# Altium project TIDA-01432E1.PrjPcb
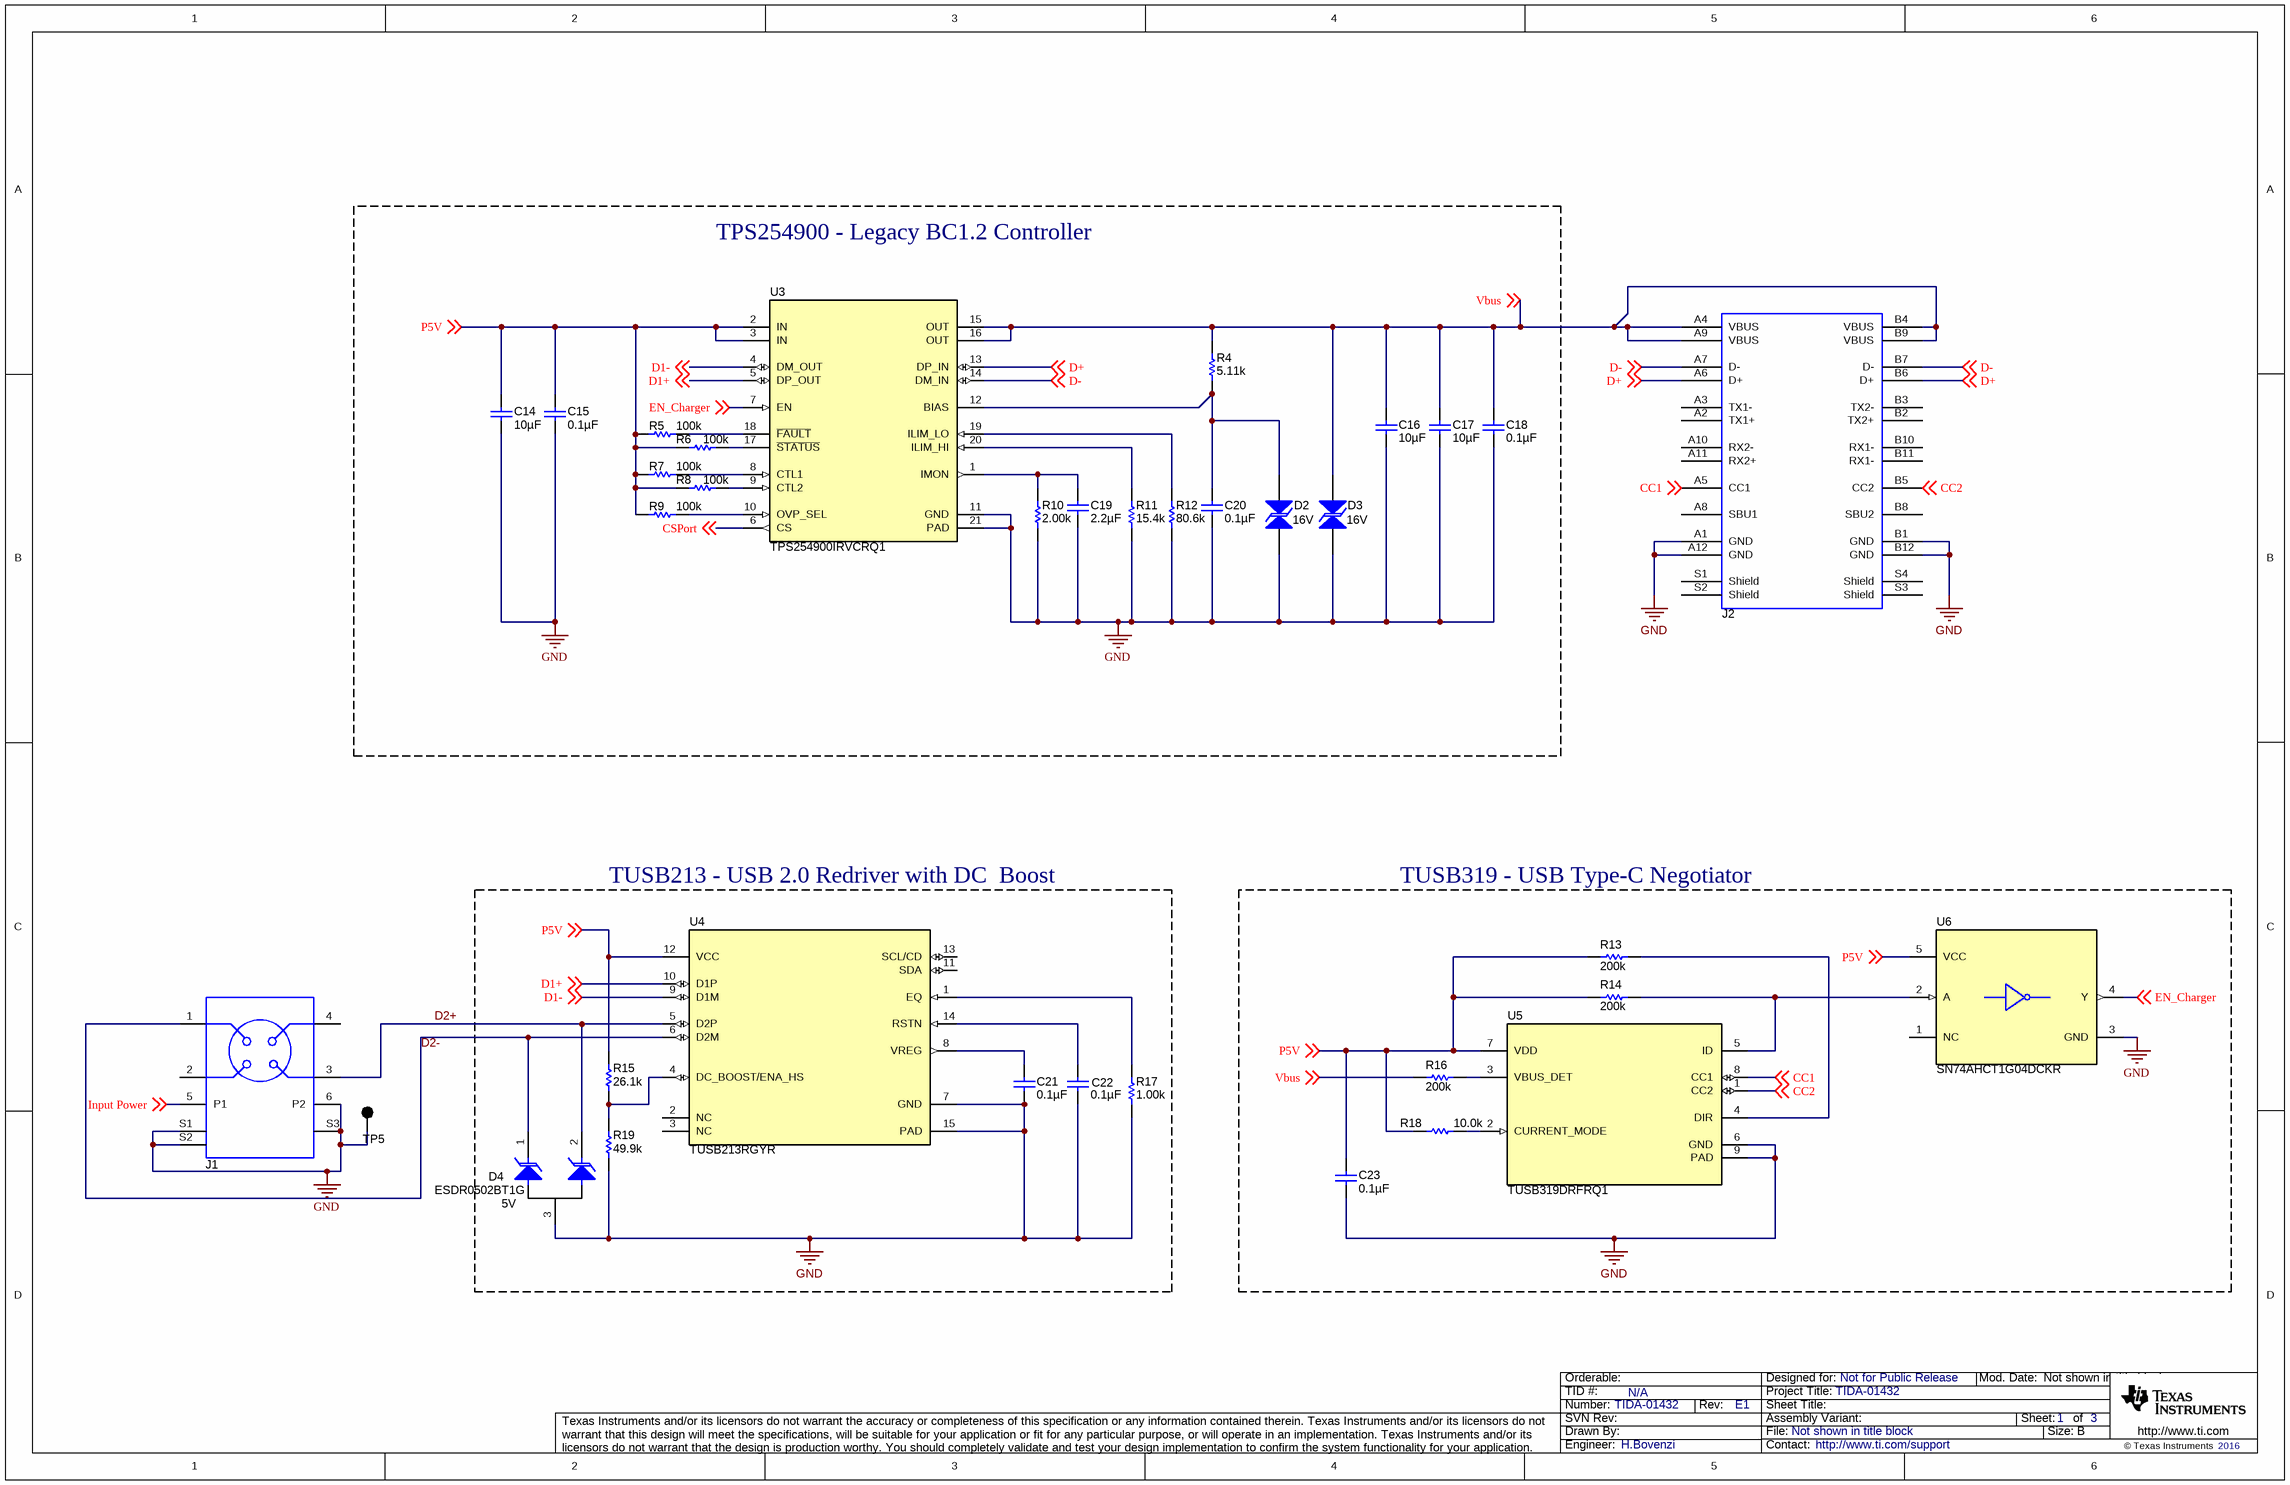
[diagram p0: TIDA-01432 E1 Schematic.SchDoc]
CopyrightYear: 2016; PCB_Layout: Bovenzi/Clanin; PCB_Rev: E1; PRJ_Customer: Not for Public Release; PRJ_Engineer: H.Bovenzi; PRJ_Number: TIDA-01432; PRJ_Title: TIDA-01432; SCH_Rev: E1; TechSupport: http://www.ti.com/support; TID: N/A
3 sheets, 89 parts. Net scope: global (net labels, ports and power ports of the same name join across sheets).
Board file: TIDA-01432_E1.PcbDoc
Sheets:
  TIDA-01432 E1 Schematic.SchDoc
  TIDA-01432 E1 Power Schematic.SchDoc
  TIDA-01432 E1_Hardware.SchDoc

## Sheet TIDA-01432 E1 Schematic.SchDoc
size 431 x 279 mm; Date: Not shown in title block; ApprovedBy: Not shown in title block; CheckedBy: Not shown in title block; Author: Not shown in title block; CompanyName: Not shown in title block; Engineer: Not shown in title block; Organization: Not shown in title block; Address1: Not shown in title block; Address2: Not shown in title block; Address3: Not shown in title block; Address4: Not shown in title block; DocumentNumber: 1; Revision: Use project parameter SCH_Rev; SheetNumber: 1; SheetTotal: 3; PageSetup: Record=PageOptions¦CenterHorizontal=True¦CenterVertical=True¦PrintScale=1.00¦XCorrection=1.00¦YCorrection=1.00¦PrintKind=0¦BorderSize=5000000¦LeftOffset=0¦BottomOffset=0¦Orientation=2¦PaperLength=1000¦PaperWidth=1000¦Scale=100¦PaperSource=15¦PrintQuality=600¦MediaType=1¦DitherType=10¦PaperKind=Letter¦PrintScaleMode=1

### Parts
C14  ValueDisplayed: 10µF  [1206_190]  (hidden comment: GCM31CR71A106KA64L)
C15  ValueDisplayed: 0.1µF  [0603L]  (hidden comment: GCM188R71H104KA57D)
C16  ValueDisplayed: 10µF  [1206_190]  (hidden comment: GCM31CR71A106KA64L)
C17  ValueDisplayed: 10µF  [1206_190]  (hidden comment: GCM31CR71A106KA64L)
C18  ValueDisplayed: 0.1µF  [0603L]  (hidden comment: GCM188R71H104KA57D)
C19  ValueDisplayed: 2.2µF  [0402S]  (hidden comment: C1005X5R1E225K050BC)
C20  ValueDisplayed: 0.1µF  [0603L]  (hidden comment: GCM188R71H104KA57D)
C21  ValueDisplayed: 0.1µF  [0603L]  (hidden comment: GCM188R71H104KA57D)
C22  ValueDisplayed: 0.1µF  [0603L]  (hidden comment: GCM188R71H104KA57D)
C23  ValueDisplayed: 0.1µF  [0603L]  (hidden comment: GCM188R71H104KA57D)
D2  value 16V  [SMA]  (hidden comment: SMAJ16CA)
D3  value 16V  [SMA]  (hidden comment: SMAJ16CA)
D4  ESDR0502BT1G  value 5V  [SOT-416]
J1  99S20D-40MA5-D  [Rosenberger_99S20D-40MA5-D]  (value not drawn)
J2  201267-0001  [Molex_201267-0001]  (value not drawn)
R4  ValueDisplayed: 5.11k  [0402S]  (hidden comment: CRCW04025K11FKED)
R5  ValueDisplayed: 100k  [0402S]  (hidden comment: RMCF0402FT100K)
R6  ValueDisplayed: 100k  [0402S]  (hidden comment: RMCF0402FT100K)
R7  ValueDisplayed: 100k  [0402S]  (hidden comment: RMCF0402FT100K)
R8  ValueDisplayed: 100k  [0402S]  (hidden comment: RMCF0402FT100K)
R9  ValueDisplayed: 100k  [0402S]  (hidden comment: RMCF0402FT100K)
R10  ValueDisplayed: 2.00k  [0402S]  (hidden comment: CRCW04022K00FKED)
R11  ValueDisplayed: 15.4k  [0402S]  (hidden comment: CRCW040215K4FKED)
R12  ValueDisplayed: 80.6k  [0402S]  (hidden comment: CRCW040280K6FKED)
R13  ValueDisplayed: 200k  [0402S]  (hidden comment: CRCW0402200KFKED)
R14  ValueDisplayed: 200k  [0402S]  (hidden comment: CRCW0402200KFKED)
R15  ValueDisplayed: 26.1k  [0402S]  (hidden comment: CRCW040226K1FKED)
R16  ValueDisplayed: 200k  [0402S]  (hidden comment: CRCW0402200KFKED)
R17  ValueDisplayed: 1.00k  [0402S]  (hidden comment: CRCW04021K00FKED)
R18  ValueDisplayed: 10.0k  [0402S]  (hidden comment: CRCW040210K0FKED)
R19  ValueDisplayed: 49.9k  [0402S]  (hidden comment: CRCW040249K9FKED)
TP5  5001  [Keystone5001]  (value not drawn)
U3  TPS254900IRVCRQ1  [RVC0020A]
U4  TUSB213RGYR  [RGY0014A]
U5  TUSB319DRFRQ1  [DRF0008A]
U6  SN74AHCT1G04DCKR  [DCK0005A_N]

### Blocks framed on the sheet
TPS254900 - Legacy BC1.2 Controller: C14-C20 D2 D3 R4-R12 U3
TUSB213 - USB 2.0 Redriver with DC  Boost: C21 C22 D4 R15 R17 R19 U4
TUSB319 - USB Type-C Negotiator: C23 R13 R14 R16 R18 U5 U6

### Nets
GND: C14.2 C15.2 C16.2 C17.2 C18.2 C19.2 C20.2 C21.2 C22.2 C23.2 D2.1 D3.1 D4.3(A) J1.6(P2) J1.S1 J1.S2 J1.S3 J2.A1(GND) J2.A12(GND) J2.B1(GND) J2.B12(GND) R10.1 R11.1 R12.1 R17.1 R19.1 TP5.1 U3.11(GND) U3.21(PAD) U4.7(GND) U4.15(PAD) U5.6(GND) U5.9(PAD) U6.3(GND)
CC1: J2.A5(CC1) U5.8(CC1) ; off-sheet CC1
CC2: J2.B5(CC2) U5.1(CC2) ; off-sheet CC2
CSPort: U3.6(CS) ; off-sheet CSPort
D1+: U3.5(DP_OUT) U4.10(D1P) ; off-sheet D1+
D1-: U3.4(DM_OUT) U4.9(D1M) ; off-sheet D1-
D2+: D4.2(C) J1.3 U4.5(D2P)
D2-: D4.1(C) J1.1 U4.6(D2M)
D+: J2.A6(D+) J2.B6(D+) U3.13(DP_IN) ; off-sheet D+
D-: J2.A7(D-) J2.B7(D-) U3.14(DM_IN) ; off-sheet D-
EN_Charger: U3.7(EN) U6.4(Y) ; off-sheet EN_Charger
Input Power: J1.5(P1) ; off-sheet Input Power
P5V: C14.1 C15.1 C23.1 R5.1 R6.1 R7.1 R8.1 R9.1 R13.2 R14.2 R15.2 R18.2 U3.2(IN) U3.3(IN) U4.12(VCC) U5.7(VDD) U6.5(VCC) ; off-sheet P5V
Vbus: C16.1 C17.1 C18.1 D3.2 J2.A4(VBUS) J2.A9(VBUS) J2.B4(VBUS) J2.B9(VBUS) R4.2 R16.1 U3.15(OUT) U3.16(OUT) ; off-sheet Vbus
NetC19_1: C19.1 R10.2 U3.1(IMON)
NetC20_1: C20.1 D2.2 R4.1 U3.12(BIAS)
NetC21_1: C21.1 U4.8(VREG)
NetC22_1: C22.1 U4.14(RSTN)
NetR5_2: R5.2 U3.18(~{FAULT})
NetR6_2: R6.2 U3.17(~{STATUS})
NetR7_2: R7.2 U3.8(CTL1)
NetR8_2: R8.2 U3.9(CTL2)
NetR9_2: R9.2 U3.10(OVP_SEL)
NetR11_2: R11.2 U3.20(ILIM_HI)
NetR12_2: R12.2 U3.19(ILIM_LO)
NetR13_1: R13.1 U5.4(DIR)
NetR14_1: R14.1 U5.5(ID) U6.2(A)
NetR15_1: R15.1 R19.2 U4.4(DC_BOOST/ENA_HS)
NetR16_2: R16.2 U5.3(VBUS_DET)
NetR17_2: R17.2 U4.1(EQ)
NetR18_1: R18.1 U5.2(CURRENT_MODE)

Not connected (* = marked no-connect by the designer): J1 2 4; J2 A2(TX1+) A3(TX1-) A8(SBU1) A10(RX2-) A11(RX2+) B2(TX2+) B3(TX2-) B8(SBU2) B10(RX1-) B11(RX1-) S1(Shield) S2(Shield) S3(Shield) S4(Shield); U4 2(NC) 3(NC) 11(SDA) 13(SCL/CD); U6 1(NC)

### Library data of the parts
C14 C16 C17 = GCM31CR71A106KA64L: CAP, CERM, 10 µF, 10 V, +/- 10%, X7R, AEC-Q200 Grade 1, 1206_190; Manufacturer: MuRata; Polarized: N; CompType: Capacitor; Value: 10uF; U/M: EA; Cap_F: 0.00001; Tolerance_%: 10; Value1: Unknown; Value2: 10V; TaMin_C: -55; TaMax_C: 125; Cap_Case: 1206; AEC Category: Q200; AEC Qualified: Y; AEC Grade: 1
C15 C18 C20-C23 = GCM188R71H104KA57D: CAP, CERM, 0.1 µF, 50 V, +/- 10%, X7R, 0603; Manufacturer: MuRata; Polarized: N; CompType: Capacitor; Value: 0.1uF; U/M: EA; Cap_F: 0.0000001; Tolerance_%: 10; ESR_ohm: 0.02; Value1: 0.02 ohm; VDC_V: 50; Value2: 50V; IRMS_A: 1.84; TaMin_C: -55; TaMax_C: 125; Cap_Case: 0603; AEC Category: Q200
C19 = C1005X5R1E225K050BC: CAP, CERM, 2.2 µF, 25 V, +/- 10%, X5R, 0402; Manufacturer: TDK; Polarized: N; CompType: Capacitor; Value: 2.2uF; U/M: EA; Cap_F: 0.0000022; Tolerance_%: 10; Value1: Unknown; VDC_V: 25; Value2: 25V; TaMin_C: -55; TaMax_C: 85; Cap_Case: 0402; SizeArea_mm2: 0.5; SizeAreaWB_mm2: 3; SizeX_mm: 1; SizeZ_mm: 0.6; AEC Category: Q200
D2 D3 = SMAJ16CA: Diode, TVS, Bi, 16 V, 400 W, SMA; Manufacturer: Littelfuse; U/M: EA; Power_W: 400; Vr_V: 16; Value1: 400W; RJA_CperW: 120; AEC Category: Q101
D4 = ESDR0502BT1G: Diode, TVS, Uni, 5 V, 20 W, AEC-Q101, SOT-416; Manufacturer: ON Semiconductor; SymbolCreator: Altium; U/M: EA; Power_W: 20; Vr_V: 5; Value1: 20W; AEC Category: Q101; AEC Qualified: Y
J1 = 99S20D-40MA5-D: RF Coaxial Connector, Bordeaux, R/A, TH; Manufacturer: Rosenberger; SymbolCreator: Altium; CompType: Plug; Gender: Male; Shrouded: Y; ContactFinish: Gold; Voltage_V: 100
J2 = 201267-0001: Receptacle, USB TYPE C, R/A, SMT; Manufacturer: Molex; SymbolCreator: Altium; CompType: Connector; Gender: Female; Row_Count: 2; ContactFinish: Gold; Cert_UL: Y
R4 = CRCW04025K11FKED: RES, 5.11 k, 1%, 0.063 W, 0402; Manufacturer: Vishay-Dale; CompType: Resistor; Value: 5.11k; Res_ohm: 5110; Value_Code: 5k11; Tolerance_%: 1; Power_W: 0.063; Value2: 0.063W; VDC_V: 50; TempCo: 100 ppm/C; EIA_Code: E96; U/M: EA; AEC Category: Q200
R5-R9 = RMCF0402FT100K: RES, 100 k, 1%, 0.063 W, AEC-Q200 Grade 0, 0402; Manufacturer: Stackpole Electronics Inc; CompType: Resistor; Value: 100k; Res_ohm: 100000; Tolerance_%: 1; Power_W: 0.063; Value2: 0.063W; VDC_V: 50; TempCo: 100 ppm/C; SizeArea_mm2: 0.5; SizeZ_mm: 0.6; EIA_Code: E96; U/M: EA; AEC Category: Q200; AEC Qualified: Y; AEC Grade: 0
R10 = CRCW04022K00FKED: RES, 2.00 k, 1%, 0.063 W, 0402; Manufacturer: Vishay-Dale; CompType: Resistor; Value: 2.00k; Res_ohm: 2000; Value_Code: 2k00; Tolerance_%: 1; Power_W: 0.063; Value2: 0.063W; VDC_V: 50; TempCo: 100 ppm/C; EIA_Code: E96; U/M: EA; AEC Category: Q200
R11 = CRCW040215K4FKED: RES, 15.4 k, 1%, 0.063 W, 0402; Manufacturer: Vishay-Dale; CompType: Resistor; Value: 15.4k; Res_ohm: 15400; Value_Code: 15k4; Tolerance_%: 1; Power_W: 0.063; Value2: 0.063W; VDC_V: 50; TempCo: 100 ppm/C; EIA_Code: E96; U/M: EA; AEC Category: Q200
R12 = CRCW040280K6FKED: RES, 80.6 k, 1%, 0.063 W, 0402; Manufacturer: Vishay-Dale; CompType: Resistor; Value: 80.6k; Res_ohm: 80600; Value_Code: 80k6; Tolerance_%: 1; Power_W: 0.063; Value2: 0.063W; VDC_V: 50; TempCo: 100 ppm/C; EIA_Code: E96; U/M: EA; AEC Category: Q200
R13 R14 R16 = CRCW0402200KFKED: RES, 200 k, 1%, 0.063 W, 0402; Manufacturer: Vishay-Dale; CompType: Resistor; Value: 200k; Res_ohm: 200000; Tolerance_%: 1; Power_W: 0.063; Value2: 0.063W; VDC_V: 50; TempCo: 100 ppm/C; EIA_Code: E96; U/M: EA; AEC Category: Q200; SizeArea_mm2: 0.5; SizeZ_mm: 0.6
R15 = CRCW040226K1FKED: RES, 26.1 k, 1%, 0.063 W, 0402; Manufacturer: Vishay-Dale; CompType: Resistor; Value: 26.1k; Res_ohm: 26100; Value_Code: 26k1; Tolerance_%: 1; Power_W: 0.063; Value2: 0.063W; VDC_V: 50; TempCo: 100 ppm/C; SizeArea_mm2: 0.5; SizeZ_mm: 0.6; EIA_Code: E96; U/M: EA; AEC Category: Q200
R17 = CRCW04021K00FKED: RES, 1.00 k, 1%, 0.063 W, 0402; Manufacturer: Vishay-Dale; CompType: Resistor; Value: 1.00k; Res_ohm: 1000; Value_Code: 1k00; Tolerance_%: 1; Power_W: 0.063; Value2: 0.063W; VDC_V: 50; TempCo: 100 ppm/C; EIA_Code: E96; U/M: EA; AEC Category: Q200
R18 = CRCW040210K0FKED: RES, 10.0 k, 1%, 0.063 W, 0402; Manufacturer: Vishay-Dale; CompType: Resistor; Value: 10.0k; Res_ohm: 10000; Value_Code: 10k0; Tolerance_%: 1; Power_W: 0.063; Value2: 0.063W; VDC_V: 50; TempCo: 100 ppm/C; EIA_Code: E96; U/M: EA; AEC Category: Q200
R19 = CRCW040249K9FKED: RES, 49.9 k, 1%, 0.063 W, 0402; Manufacturer: Vishay-Dale; CompType: Resistor; Value: 49.9k; Res_ohm: 49900; Value_Code: 49k9; Tolerance_%: 1; Power_W: 0.063; Value2: 0.063W; VDC_V: 50; TempCo: 100 ppm/C; SizeArea_mm2: 0.5; SizeZ_mm: 0.6; EIA_Code: E96; U/M: EA; AEC Category: Q200
TP5 = 5001: Test Point, Miniature, Black, TH; Manufacturer: Keystone; CompType: Test Point Loop; ContactFinish: Silver; Green_Lifecycle: Active; Green_REACh: Passed
U3 = TPS254900IRVCRQ1: Automotive USB Charging Port Controller and Power Switch with Short to BAT protection, RVC0020A; Alternate PartNumber: TPS254900IRVCTQ1; Manufacturer: Texas Instruments; SymbolCreator: Altium; CompType: IC; U/M: EA
U4 = TUSB213RGYR: USB 2.0 HIGH SPEED SIGNAL CONDITIONER, RGY0014A (VQFN-14); Alternate PartNumber: TUSB213RGYT; Manufacturer: Texas Instruments; SymbolCreator: Altium; SizeArea_mm2: 12.25; SizeAreaWB_mm2: 20.25; SizeX_mm: 3.5; SizeZ_mm: 1; CompType: IC; U/M: EA
U5 = TUSB319DRFRQ1: USB Type-C DFP Port Controller, DRF0008A; Manufacturer: Texas Instruments; SymbolCreator: Altium; CompType: IC; U/M: EA
U6 = SN74AHCT1G04DCKR: Single Inverter Gate, DCK0005A (SOT-5); Alternate PartNumber: SN74AHCT1G04DCKT; Manufacturer: Texas Instruments; SymbolCreator: a0411947; SizeArea_mm2: 4.2; SizeAreaWB_mm2: 9.3; SizeX_mm: 2.1; SizeY_mm: 2; SizeZ_mm: 1.1; CompType: IC; U/M: EA

## Sheet TIDA-01432 E1 Power Schematic.SchDoc
size 431 x 279 mm; Date: Not shown in title block; ApprovedBy: Not shown in title block; CheckedBy: Not shown in title block; Author: Not shown in title block; CompanyName: Not shown in title block; Engineer: Not shown in title block; Organization: Not shown in title block; Address1: Not shown in title block; Address2: Not shown in title block; Address3: Not shown in title block; Address4: Not shown in title block; DocumentNumber: 1; Revision: Use project parameter SCH_Rev; SheetNumber: 2; SheetTotal: 3; PageSetup: Record=PageOptions¦CenterHorizontal=True¦CenterVertical=True¦PrintScale=1.00¦XCorrection=1.00¦YCorrection=1.00¦PrintKind=0¦BorderSize=5000000¦LeftOffset=0¦BottomOffset=0¦Orientation=2¦PaperLength=1000¦PaperWidth=1000¦Scale=100¦PaperSource=15¦PrintQuality=600¦MediaType=1¦DitherType=10¦PaperKind=Letter¦PrintScaleMode=1
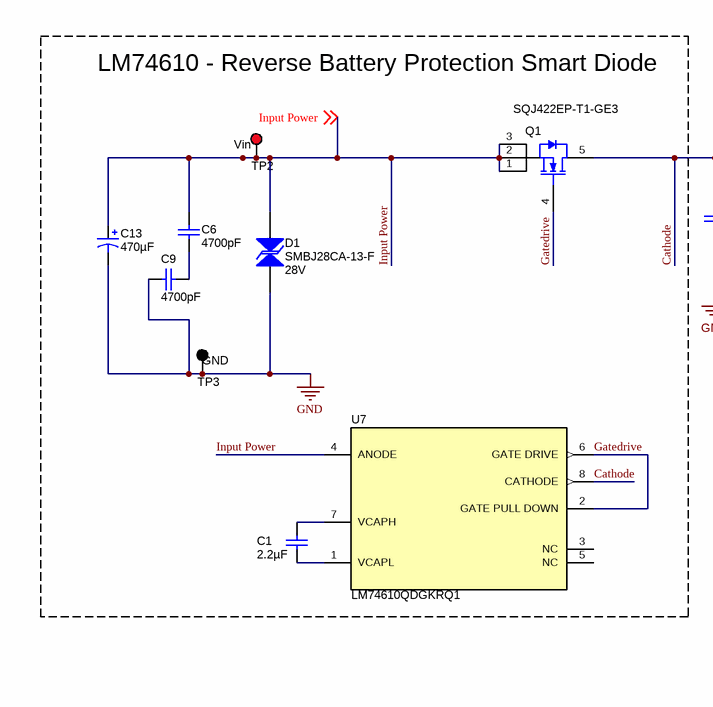
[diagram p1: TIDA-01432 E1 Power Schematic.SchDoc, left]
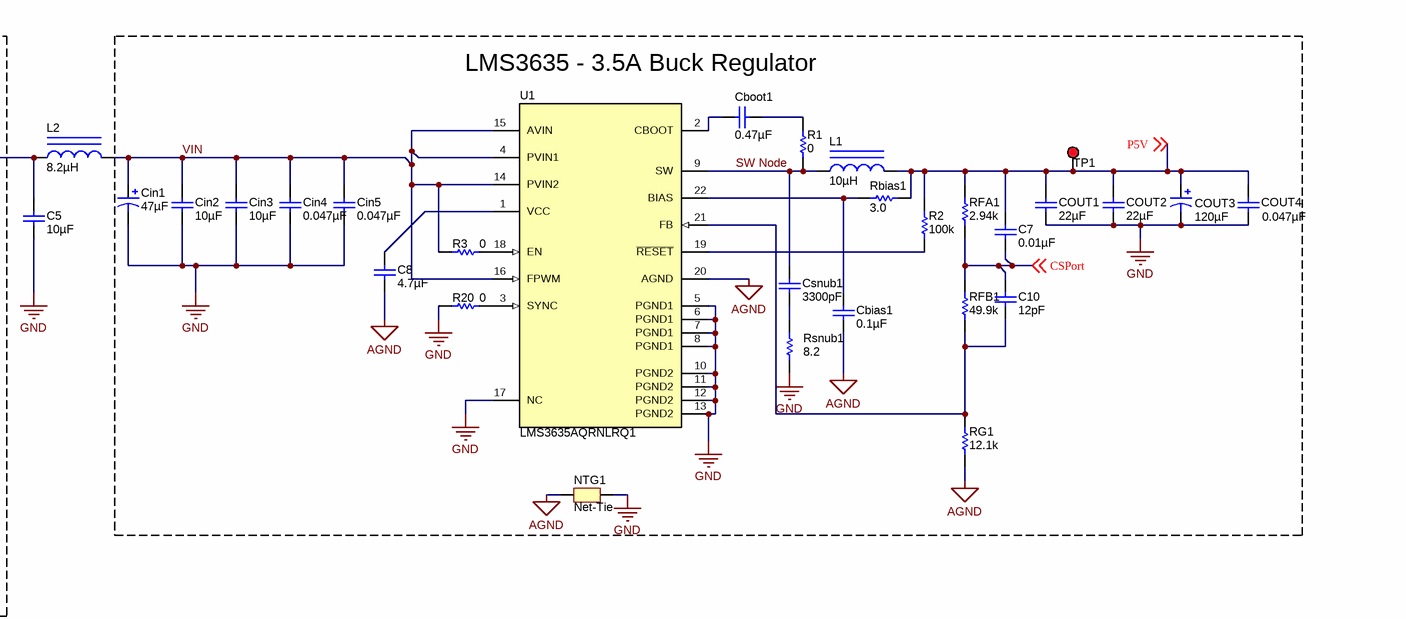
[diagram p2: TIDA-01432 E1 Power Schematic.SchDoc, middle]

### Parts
C1  ValueDisplayed: 2.2µF  [0805_HV]  (hidden comment: C2012X5R1H225K125AB)
C5  ValueDisplayed: 10µF  [1210]  (hidden comment: GRM32ER71H106KA12L)
C6  ValueDisplayed: 4700pF  [0603]  (hidden comment: C0603C472J1GAC7867)
C7  ValueDisplayed: 0.01µF  [0402]  (hidden comment: GRM155R61A103KA01D)
C8  ValueDisplayed: 4.7µF  [0603]  (hidden comment: C1608X5R1V475K080AC)
C9  ValueDisplayed: 4700pF  [0603]  (hidden comment: C0603C472J1GAC7867)
C10  ValueDisplayed: 12pF  [0402S]  (hidden comment: C0402C120J3GACAUTO)
C13  ValueDisplayed: 470µF  [CAPSMT_62_KG5]  (hidden comment: EMVA500ATR471MKG5S)
Cbias1  ValueDisplayed: 0.1µF  [0402S]  (hidden comment: C1005X7R1H104K050BB)
Cboot1  ValueDisplayed: 0.47µF  [0402]  (hidden comment: C1005X5R1A474K050BB)
Cin1  ValueDisplayed: 47µF  [SM_RADIAL_F]  (hidden comment: EEE-FK1J470P)
Cin2  ValueDisplayed: 10µF  [1210]  (hidden comment: GRM32ER71H106KA12L)
Cin3  ValueDisplayed: 10µF  [1210]  (hidden comment: GRM32ER71H106KA12L)
Cin4  ValueDisplayed: 0.047µF  [0603]  (hidden comment: GRM188R71H473KA61D)
Cin5  ValueDisplayed: 0.047µF  [0603]  (hidden comment: GRM188R71H473KA61D)
COUT1  ValueDisplayed: 22µF  [1210_270]  (hidden comment: GRM32ER61E226KE15L)
COUT2  ValueDisplayed: 22µF  [1210_270]  (hidden comment: GRM32ER61E226KE15L)
COUT3  ValueDisplayed: 120µF  [CAPSMT_62_F61]  (hidden comment: APXE100ARA121MF61G)
COUT4  ValueDisplayed: 0.047µF  [0603]  (hidden comment: GCM188R71E473KA37D)
Csnub1  ValueDisplayed: 3300pF  [0201]  (hidden comment: GRM033R61A332KA01D)
D1  SMBJ28CA-13-F  value 28V  [SMB-Bi]
L1  ValueDisplayed: 10µH  [XAL5050]  (hidden comment: XAL5050-103MEB)
L2  ValueDisplayed: 8.2µH  [SRP6540]  (hidden comment: SRP6540-8R2M)
NTG1  Net-Tie  [Net-Tie_50milWide_30milLong]  (net tie, no BOM)
Q1  SQJ422EP-T1-GE3  [PowerPAK_SO-8L]
R1  ValueDisplayed: 0  [0402S]  (hidden comment: CRCW04020000Z0ED)
R2  ValueDisplayed: 100k  [0402S]  (hidden comment: CRCW0805100KFKEA)
R3  ValueDisplayed: 0  [0402S]  (hidden comment: MCR01MZPJ000)
R20  ValueDisplayed: 0  [0402S]  (hidden comment: MCR01MZPJ000)
Rbias1  ValueDisplayed: 3.0  [0402]  (hidden comment: CRCW04023R00JNED)
RFA1  ValueDisplayed: 2.94k  [0402S]  (hidden comment: CRCW04022K94FKED)
RFB1  ValueDisplayed: 49.9k  [0402S]  (hidden comment: ERJ-2RKF4992X)
RG1  ValueDisplayed: 12.1k  [0402S]  (hidden comment: CRCW040212K1FKED)
Rsnub1  ValueDisplayed: 8.2  [0402S]  (hidden comment: CRCW04028R20JNED)
TP1  5000  [Keystone5000]  (value not drawn)
TP2  5000  [Keystone5000]  (value not drawn)
TP3  5001  [Keystone5001]  (value not drawn)
U1  LMS3635AQRNLRQ1  [RNL0022A_NV]
U7  LM74610QDGKRQ1  [DGK0008A_N]

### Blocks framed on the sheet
LM74610 - Reverse Battery Protection Smart Diode: C1 C6 C9 C13 D1 Q1 TP2 TP3 U7
LMS3635 - 3.5A Buck Regulator: C7 C8 C10 Cbias1 Cboot1 Cin1-Cin5 COUT1-COUT4 Csnub1 L1 NTG1 R1-R3 R20 Rbias1 RFA1 RFB1 RG1 Rsnub1 TP1 U1

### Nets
AGND: C8.2 Cbias1.1 NTG1.1 RG1.1 U1.20(AGND)
GND: C5.2 C9.1 C13.2(-) Cin1.2(-) Cin2.2 Cin3.2 Cin4.2 Cin5.2 COUT1.1 COUT2.1 COUT3.2(-) COUT4.2 D1.2 NTG1.2 R20.2 Rsnub1.1 TP3.1 U1.5(PGND1) U1.6(PGND1) U1.7(PGND1) U1.8(PGND1) U1.10(PGND2) U1.11(PGND2) U1.12(PGND2) U1.13(PGND2) U1.17(NC)
Cathode: C5.1 L2.1 Q1.5(D) U7.8(CATHODE)
CSPort: C7.2 C10.1 RFA1.1 RFB1.1 ; off-sheet CSPort
Gatedrive: Q1.4(G) U7.2(GATE_PULL_DOWN) U7.6(GATE_DRIVE)
Input Power: C6.1 C13.1(+) D1.1 Q1.1(S) Q1.2(S) Q1.3(S) TP2.1 U7.4(ANODE) ; off-sheet Input Power
P5V: C7.1 COUT1.2 COUT2.2 COUT3.1(+) COUT4.1 L1.2 R2.1 Rbias1.2 RFA1.2 TP1.1 ; off-sheet P5V
SW Node: Csnub1.2 L1.1 R1.1 U1.9(SW)
VIN: Cin1.1(+) Cin2.1 Cin3.1 Cin4.1 Cin5.1 L2.2 R3.2 U1.4(PVIN1) U1.14(PVIN2) U1.15(AVIN) U1.16(FPWM)
NetC1_1: C1.1 U7.7(VCAPH)
NetC1_2: C1.2 U7.1(VCAPL)
NetC6_2: C6.2 C9.2
NetC8_1: C8.1 U1.1(VCC)
NetC10_2: C10.2 RFB1.2 RG1.2 U1.21(FB)
NetCbias1_2: Cbias1.2 Rbias1.1 U1.22(BIAS)
NetCboot1_1: Cboot1.1 R1.2
NetCboot1_2: Cboot1.2 U1.2(CBOOT)
NetCsnub1_1: Csnub1.1 Rsnub1.2
NetR2_2: R2.2 U1.19(~{RESET})
NetR3_1: R3.1 U1.18(EN)
NetR20_1: R20.1 U1.3(SYNC)

Not connected (* = marked no-connect by the designer): U7 3(NC) 5(NC)

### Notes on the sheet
- (near TP2) Vin
- (near TP3) GND

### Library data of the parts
C1 = C2012X5R1H225K125AB: CAP, CERM, 2.2 µF, 50 V, +/- 10%, X5R, 0805; Manufacturer: TDK; CompType: Capacitor; Value: 2.2uF; Polarized: N; U/M: EA; Cap_F: 0.0000022; Tolerance_%: 10; Value1: Unknown; VDC_V: 50; Value2: 50V; TaMin_C: -55; TaMax_C: 85; Cap_Case: 0805
C5 = GRM32ER71H106KA12L: CAP, CERM, 10uF, 50V, +/-10%, X7R, 1210; Manufacturer: MuRata; Polarized: N; CompType: Capacitor; U/M: EA; Cap_F: 0.00001; Tolerance_%: 10; Value1: Unknown; VDC_V: 50; TaMin_C: -55; TaMax_C: 125
C6 C9 = C0603C472J1GAC7867: CAP, CERM, 4700 pF, 100 V, +/- 5%, C0G/NP0, 0603; Manufacturer: Kemet; Polarized: N; CompType: Capacitor; Value: 4700pF; U/M: EA; Cap_F: 0.0000000047; Tolerance_%: 5; Value1: Unknown; VDC_V: 100; Value2: 100V; TaMin_C: -55; TaMax_C: 125; SizeArea_mm2: 1.28; SizeAreaWB_mm2: 4.68; SizeX_mm: 1.6; SizeY_mm: 0.8; SizeZ_mm: 1; AEC Category: Q200
C7 = GRM155R61A103KA01D: CAP, CERM, 0.01 µF, 10 V, +/- 10%, X5R, 0402; Manufacturer: MuRata; Polarized: N; CompType: Capacitor; Value: 0.01uF; U/M: EA; Cap_F: 0.00000001; Tolerance_%: 10; Value1: Unknown; Value2: 10V; TaMin_C: -55; TaMax_C: 85; SizeArea_mm2: 0.5; SizeAreaWB_mm2: 3; SizeX_mm: 1; SizeZ_mm: 0.6; AEC Category: Q200
C8 = C1608X5R1V475K080AC: CAP, CERM, 4.7 µF, 35 V, +/- 10%, X5R, 0603; Manufacturer: TDK; Polarized: N; CompType: Capacitor; Value: 4.7uF; Tolerance_%: 10; ESR_ohm: 0.003728; Value1: 0.003728 ohm; Value2: 35V; U/M: EA; Cap_F: 0.0000047; VDC_V: 35; IRMS_A: 2.69359; TaMin_C: -55; TaMax_C: 85; AEC Category: Q200; SizeArea_mm2: 1.28; SizeAreaWB_mm2: 4.68; SizeX_mm: 1.6; SizeY_mm: 0.8; SizeZ_mm: 1
C10 = C0402C120J3GACAUTO: CAP, CERM, 12 pF, 25 V, +/- 5%, C0G/NP0, AEC-Q200 Grade 1, 0402; Manufacturer: Kemet; Polarized: N; CompType: Capacitor; Value: 12pF; U/M: EA; Cap_F: 0.000000000012; Tolerance_%: 5; Value1: Unknown; VDC_V: 25; Value2: 25V; TaMin_C: -55; TaMax_C: 125; Cap_Case: 0402; AEC Category: Q200; AEC Qualified: Y; AEC Grade: 1
C13 = EMVA500ATR471MKG5S: CAP, AL, 470 µF, 50 V, +/- 20%, SMD; Manufacturer: Chemi-Con; Polarized: Y; CompType: Capacitor; Value: 470uF; U/M: EA; Cap_F: 0.00047; Tolerance_%: 20; Value1: Unknown; VDC_V: 50; Value2: 50V; IRMS_A: 0.74; TaMin_C: -40; TaMax_C: 85; Cap_Case: KG5; SizeAreaWB_mm2: 225; SizeArea_mm2: 169; SizeX_mm: 13; SizeZ_mm: 16; AEC Category: Q200
Cbias1 = C1005X7R1H104K050BB: CAP, CERM, 0.1 µF, 50 V, +/- 10%, X7R, 0402; Manufacturer: TDK; Polarized: N; CompType: Capacitor; Value: 0.1uF; U/M: EA; Cap_F: 0.0000001; Tolerance_%: 10; Value1: Unknown; VDC_V: 50; Value2: 50V; TaMin_C: -55; TaMax_C: 125; Cap_Case: 0402
Cboot1 = C1005X5R1A474K050BB: CAP, CERM, 0.47 µF, 10 V, +/- 10%, X5R, 0402; Manufacturer: TDK; Polarized: N; CompType: Capacitor; Value: 0.47uF; U/M: EA; Cap_F: 0.00000047; Tolerance_%: 10; Value1: Unknown; Value2: 10V; TaMin_C: -55; TaMax_C: 85; AEC Category: Q200
Cin1 = EEE-FK1J470P: CAP, AL, 47 µF, 63 V, +/- 20%, 0.65 ohm, SMD; Manufacturer: Panasonic; Polarized: Y; CompType: Capacitor; Value: 47uF; U/M: EA; Cap_F: 0.000047; Tolerance_%: 20; VDC_V: 63; Value2: 63V; ESR_ohm: 0.65; IRMS_A: 0.25; TaMin_C: -55; TaMax_C: 105; Cap_Case: F; AEC Category: Q200
Cin2 Cin3 = GRM32ER71H106KA12L: CAP, CERM, 10 µF, 50 V, +/- 10%, X7R, 1210; Manufacturer: MuRata; Polarized: N; CompType: Capacitor; Value: 10uF; U/M: EA; Cap_F: 0.00001; Tolerance_%: 10; Value1: Unknown; VDC_V: 50; Value2: 50V; TaMin_C: -55; TaMax_C: 125; AEC Category: Q200
Cin4 Cin5 = GRM188R71H473KA61D: CAP, CERM, 0.047 µF, 50 V,+/- 10%, X7R, 0603; Manufacturer: MuRata; Polarized: N; CompType: Capacitor; Value: 0.047uF; U/M: EA; Cap_F: 0.000000047; Tolerance_%: 10; Value1: Unknown; VDC_V: 50; Value2: 50V; TaMin_C: -55; TaMax_C: 125; AEC Category: Q200; SizeArea_mm2: 1.28; SizeAreaWB_mm2: 4.68; SizeX_mm: 1.6; SizeY_mm: 0.8; SizeZ_mm: 1; Green_Lifecycle: Active; Green_REACh: Passed
COUT1 COUT2 = GRM32ER61E226KE15L: CAP, CERM, 22 µF, 25 V, +/- 10%, X5R, 1210; Manufacturer: MuRata; Polarized: N; CompType: Capacitor; Value: 22uF; U/M: EA; Cap_F: 0.000022; Tolerance_%: 10; ESR_ohm: 0.002; Value1: 0.002 ohm; VDC_V: 25; Value2: 25V; IRMS_A: 3.67; TaMin_C: -55; TaMax_C: 85; Cap_Case: 1210; AEC Category: Q200; SizeArea_mm2: 8; SizeAreaWB_mm2: 14.7; SizeX_mm: 3.2; SizeY_mm: 2.5; SizeZ_mm: 2.7
COUT3 = APXE100ARA121MF61G: CAP, AL, 120 µF, 10 V, +/- 20%, 0.025 ohm, SMD; Manufacturer: Chemi-Con; Polarized: Y; CompType: Capacitor; Value: 120uF; U/M: EA; Cap_F: 0.00012; Tolerance_%: 20; VDC_V: 10; Value2: 10V; ESR_ohm: 0.025; IRMS_A: 2.53; TaMin_C: -55; TaMax_C: 105; Cap_Case: F61; SizeAreaWB_mm2: 73.96; SizeArea_mm2: 43.56; SizeX_mm: 6.6; SizeZ_mm: 5.8; AEC Category: Q200
COUT4 = GCM188R71E473KA37D: CAP, CERM, 0.047 µF, 25 V, +/- 10%, X7R, AEC-Q200 Grade 1, 0603; Manufacturer: MuRata; Polarized: N; CompType: Capacitor; Value: 0.047uF; U/M: EA; Cap_F: 0.000000047; Tolerance_%: 10; Value1: Unknown; VDC_V: 25; Value2: 25V; TaMin_C: -55; TaMax_C: 125; AEC Category: Q200; AEC Qualified: Y; AEC Grade: 1
Csnub1 = GRM033R61A332KA01D: CAP, CERM, 3300 pF, 10 V, +/- 10%, X5R, 0201; Manufacturer: MuRata; Polarized: N; CompType: Capacitor; Value: 3300pF; U/M: EA; Cap_F: 0.0000000033; Tolerance_%: 10; Value1: Unknown; Value2: 10V; TaMin_C: -55; TaMax_C: 85; SizeArea_mm2: 0.18; SizeAreaWB_mm2: 2.08; SizeX_mm: 0.6; SizeY_mm: 0.3; SizeZ_mm: 0.26; AEC Category: Q200
D1 = SMBJ28CA-13-F: Diode, TVS, Bi, 28 V, 45.4 Vc, SMB; Manufacturer: Diodes Inc.; U/M: EA; Power_W: 5; Vr_V: 28; Value1: 5W; AEC Category: Q101; AEC Qualified: N
L1 = XAL5050-103MEB: Inductor, Shielded, Composite, 10 µH, 4.9 A, 0.05 ohm, SMD; Manufacturer: Coilcraft; Value: 10uH; Ind_H: 10.0E-6; Imax_A: 4.9; Irms: 4.9A @ 40C rise; Isat: 4.9A @ 30% inductance drop; DCR_ohm: 0.05; Value2: 4.9A; AEC Category: Q200; SizeAreaWB_mm2: 54.4544; SizeArea_mm2: 28.9344; SizeX_mm: 5.28; SizeY_mm: 5.48; SizeZ_mm: 5.1
L2 = SRP6540-8R2M: Inductor, Shielded, Ferrite, 8.2 µH, 4.5 A, 0.0505 ohm, SMD; Manufacturer: Bourns; Value: 8.2uH; Ind_H: 8.2E-6; Imax_A: 4.5; Irms: 4.5A @ 40C rise; Isat: 5A @ 20% inductance drop; DCR_ohm: 0.0505; Value2: 4.5A; AEC Category: Q200; SizeAreaWB_mm2: 82.65; SizeArea_mm2: 50.25; SizeX_mm: 7.5; SizeY_mm: 6.7; SizeZ_mm: 4
NTG1 = Net-Tie: Single point connection between nets.; SymbolCreator: codlsc
Q1 = SQJ422EP-T1-GE3: MOSFET, N-CH, 40 V, 75 A, PowerPAK_SO-8L; Manufacturer: Vishay-Siliconix; Alternate Manufacturer: None; U/M: EA; ChType: N; Value: 40V; VdsMax_V: 40; Value1: 0.0043 ohm; Rdson45_ohm: 0.0043; Value2: 67 nC; QgTyp_nC: 67; Vgs_V: 20; IdsMax_A: 75; SymbolCreator: a0412235
R1 = CRCW04020000Z0ED: RES, 0, 5%, 0.063 W, 0402; Manufacturer: Vishay-Dale; CompType: Resistor; Value: 0; Value_Code: 0000; Tolerance_%: 5; Power_W: 0.063; Value2: 0.063W; VDC_V: 50; TempCo: 200 ppm/C; SizeArea_mm2: 0.5; SizeX_mm: 1; SizeZ_mm: 0.6; EIA_Code: E24; U/M: EA; AEC Category: Q200
R2 = ERJ-2RKF1001X: RES, 1.00 k, 1%, 0.1 W, 0402; Manufacturer: Panasonic; CompType: Resistor; Value: 1.00k; Res_ohm: 1000; Value_Code: 1k00; Tolerance_%: 1; Power_W: 0.1; Value2: 0.1W; VDC_V: 50; TempCo: 100 ppm/C; EIA_Code: E96; U/M: EA
R3 R20 = MCR01MZPJ000: RES, 0, 5%, 0.063 W, 0402; Manufacturer: Rohm; CompType: Resistor; Value: 0; Value_Code: 0000; Tolerance_%: 5; Power_W: 0.063; Value2: 0.063W; VDC_V: 50; TempCo: 500 ppm/C; EIA_Code: E24; U/M: EA
Rbias1 = CRCW04023R00JNED: RES, 3.0, 5%, 0.063 W, 0402; Manufacturer: Vishay-Dale; CompType: Resistor; Value: 3.0; Res_ohm: 3; Value_Code: 3R00; Tolerance_%: 5; Power_W: 0.063; Value2: 0.063W; VDC_V: 50; TempCo: 200 ppm/C; EIA_Code: E24; U/M: EA; AEC Category: Q200; SizeArea_mm2: 0.5; SizeX_mm: 1; SizeZ_mm: 0.6
RFA1 = CRCW04022K94FKED: RES, 2.94 k, 1%, 0.063 W, 0402; Manufacturer: Vishay-Dale; CompType: Resistor; Value: 2.94k; Res_ohm: 2940; Value_Code: 2k94; Tolerance_%: 1; Power_W: 0.063; Value2: 0.063W; VDC_V: 50; TempCo: 100 ppm/C; SizeArea_mm2: 0.5; SizeZ_mm: 0.6; EIA_Code: E96; U/M: EA; AEC Category: Q200
RFB1 = ERJ-2RKF4992X: RES, 49.9 k, 1%, 0.1 W, AEC-Q200 Grade 0, 0402; Manufacturer: Panasonic; CompType: Resistor; Value: 49.9k; Res_ohm: 49900; Value_Code: 49k9; Tolerance_%: 1; Power_W: 0.1; Value2: 0.1W; VDC_V: 50; TempCo: 100 ppm/C; EIA_Code: E96; U/M: EA; AEC Category: Q200; AEC Qualified: Y; AEC Grade: 0
RG1 = CRCW040212K1FKED: RES, 12.1 k, 1%, 0.063 W, 0402; Manufacturer: Vishay-Dale; CompType: Resistor; Value: 12.1k; Res_ohm: 12100; Value_Code: 12k1; Tolerance_%: 1; Power_W: 0.063; Value2: 0.063W; VDC_V: 50; TempCo: 100 ppm/C; EIA_Code: E96; U/M: EA; AEC Category: Q200
Rsnub1 = CRCW04028R20JNED: RES, 8.2, 5%, 0.063 W, 0402; Manufacturer: Vishay-Dale; CompType: Resistor; Value: 8.2; Value_Code: 8R20; Tolerance_%: 5; Power_W: 0.063; Value2: 0.063W; VDC_V: 50; TempCo: 200 ppm/C; SizeArea_mm2: 0.5; SizeX_mm: 1; SizeZ_mm: 0.6; EIA_Code: E24; U/M: EA; AEC Category: Q200
TP1 TP2 = 5000: Test Point, Miniature, Red, TH; Manufacturer: Keystone; CompType: Test Point Loop; ContactFinish: Silver
TP3 = 5001: Test Point, Miniature, Black, TH; Manufacturer: Keystone; CompType: Test Point Loop; ContactFinish: Silver
U1 = LMS3635AQRNLRQ1: LMS3635AQRNLRQ1, RNL0022A (VQFN-HR-22); Alternate PartNumber: LMS3635AQRNLTQ1; Manufacturer: Texas Instruments; SymbolCreator: Altium; SizeArea_mm2: 20; SizeAreaWB_mm2: 42; SizeX_mm: 4; SizeY_mm: 5; SizeZ_mm: 0.9; CompType: IC; U/M: EA
U7 = LM74610QDGKRQ1: Zero Iq Reverse Polarity Protection Smart Diode Controller, DGK0008A (VSSOP-8); Manufacturer: Texas Instruments; SymbolCreator: Altium; SizeArea_mm2: 15.655; SizeAreaWB_mm2: 35.955; SizeX_mm: 5.05; SizeY_mm: 3.1; SizeZ_mm: 1.1; CompType: IC; U/M: EA

## Sheet TIDA-01432 E1_Hardware.SchDoc
size 431 x 279 mm; Date: Not shown in title block; ApprovedBy: Not shown in title block; CheckedBy: Not shown in title block; Author: Not shown in title block; CompanyName: Not shown in title block; Engineer: Not shown in title block; Organization: Not shown in title block; Address1: Not shown in title block; Address2: Not shown in title block; Address3: Not shown in title block; Address4: Not shown in title block; DocumentNumber: 1; Revision: Use project parameter SCH_Rev; SheetNumber: 3; SheetTotal: 3; PageSetup: Record=PageOptions¦CenterHorizontal=True¦CenterVertical=True¦PrintScale=1.00¦XCorrection=1.00¦YCorrection=1.00¦PrintKind=0¦BorderSize=5000000¦LeftOffset=0¦BottomOffset=0¦Orientation=2¦PaperLength=1000¦PaperWidth=1000¦Scale=100¦PaperSource=15¦PrintQuality=600¦MediaType=1¦DitherType=10¦PaperKind=Letter¦PrintScaleMode=1
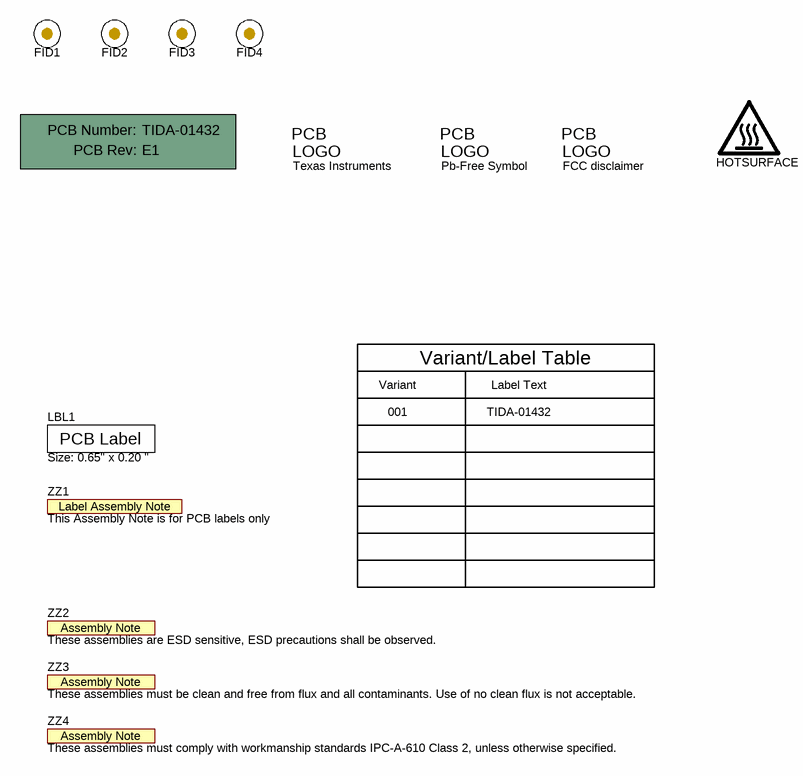
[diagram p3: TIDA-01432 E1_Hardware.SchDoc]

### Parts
!PCB  Printed Circuit Board  (value not drawn)  (mechanical)
FID1  Fiducial  [Fiducial10-20]  (value not drawn)
FID2  Fiducial  [Fiducial10-20]  (value not drawn)
FID3  Fiducial  [Fiducial10-20]  (value not drawn)
FID4  Fiducial  [Fiducial10-20]  (value not drawn)
HOTSURFACE  CAUTION HOT SURFACE  [IEC_HotSurface_Small]  (value not drawn)  (no BOM)
LBL1  Size: 0.65" x 0.20 "  [Label_650x200]
Logo1  Texas Instruments  [TI_Stacked_Overlay_Small]  (no BOM)
Logo2  Pb-Free Symbol  [Pb-Free_Overlay_Small]  (no BOM)
Logo3  FCC disclaimer  [FCC_disclaimer]  (no BOM)
ZZ1  This Assembly Note is for PCB labels only  [AssemblyNoteLabel]  (no BOM)
ZZ2  These assemblies are ESD sensitive, ESD precautions shall be observed.  [AssemblyNote]  (no BOM)
ZZ3  These assemblies must be clean and free from flux and all contaminants. Use of no clean flux is not acceptable.  [AssemblyNote]  (no BOM)
ZZ4  These assemblies must comply with workmanship standards IPC-A-610 Class 2, unless otherwise specified.  [AssemblyNote]  (no BOM)

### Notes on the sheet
- Variant
- Variant/Label Table
- Label Text
- 001
- TIDA-01432

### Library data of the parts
!PCB = PCB: Manufacturer: Any; PartNumber: TIDA-01432; SymbolCreator: a0412235
FID1-FID4 = Fiducial: Fiducial mark.  There is nothing to buy or mount.; SymbolCreator: codlsc
HOTSURFACE = IEC_HotSurface: IEC 61010-1 Hot Surface Warning; SymbolCreator: a0412235
LBL1 = THT-14-423-10: Thermal Transfer Printable Labels, 0.650" W x 0.200" H - 10,000 per roll; Manufacturer: Brady; SymbolCreator: a0412235; CompType: Label
Logo1 = TI_Logo: Texas Instrument Corporate Signature; SymbolCreator: codlsc
Logo2 = Pb-Free: SymbolCreator: a0412235
Logo3 = FCC_disclaimer: SymbolCreator: codlsc
ZZ1 = AssemblyNoteLabel: SymbolCreator: a0412235
ZZ2-ZZ4 = AssemblyNote: SymbolCreator: codlsc

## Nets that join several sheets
GND: TIDA-01432 E1 Schematic (34 pins), TIDA-01432 E1 Power Schematic (26 pins)
CSPort: TIDA-01432 E1 Schematic (U3.6), TIDA-01432 E1 Power Schematic (C7.2 C10.1 RFA1.1 RFB1.1)
Input Power: TIDA-01432 E1 Schematic (J1.5), TIDA-01432 E1 Power Schematic (8 pins)
P5V: TIDA-01432 E1 Schematic (17 pins), TIDA-01432 E1 Power Schematic (10 pins)

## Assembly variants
001: not fitted FID1 FID2 FID3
